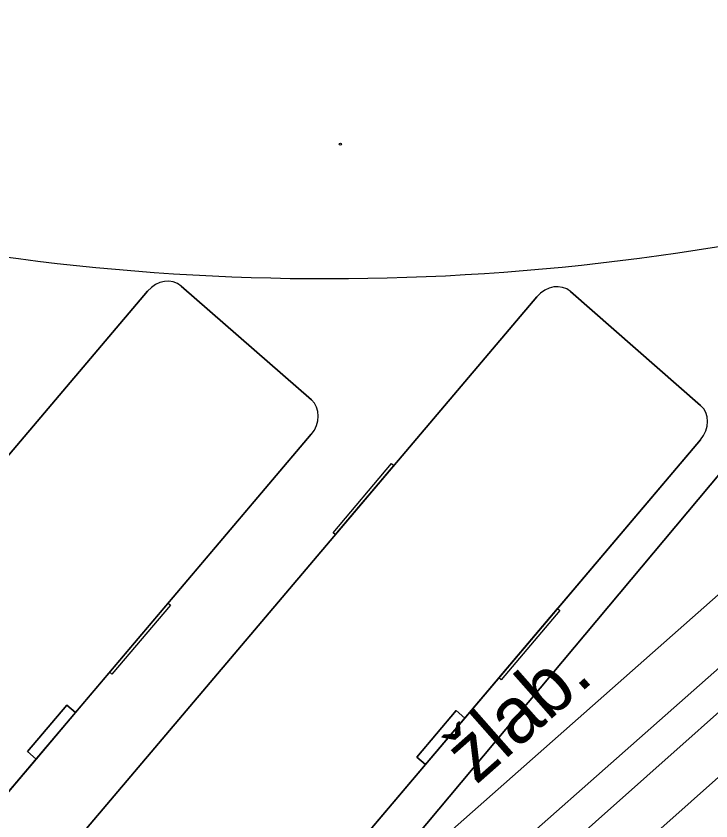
# Model space of a CAD drawing. Extents: x -438200 to -437954, y -1133133 to -1132850.
# Drawn here: x -438061.56 to -438053.53, y -1132985.78 to -1132976.48 of the extents above; entities that cross this region are included whole.
import ezdxf

# ---------------------------------------------------------------- set-up
doc = ezdxf.new("R2010")
doc.units = 0
for name, color, linetype in [('Vrstva 1', 7, 'Continuous'), ('Vrstva 10', 7, 'Continuous'), ('Vrstva 11', 7, 'Continuous'), ('Vrstva 40', 7, 'Continuous'), ('Vrstva 9', 7, 'Continuous')]:
    doc.layers.add(name, color=color, linetype=linetype)

msp = doc.modelspace()

# ---------------------------------------------------------------- linework, layer by layer
at = {"layer": 'Vrstva 1'}
for p, q in [((-438059.6486, -1132979.5983), (-438058.1432, -1132980.9139)), ((-438059.6486, -1132979.5983), (-438058.1432, -1132980.9139)), ((-438055.1494, -1132979.6617), (-438053.644, -1132980.9773)), ((-438055.1494, -1132979.6617), (-438053.644, -1132980.9773))]:
    msp.add_line(p, q, dxfattribs=at)
for points in [[(-438050.7956, -1132978.6286), (-438061.1166, -1132990.9482), (-438063.7995, -1132988.7005), (-438065.4554, -1132990.6771)], [(-438050.7956, -1132978.6286), (-438061.1166, -1132990.9482), (-438063.7995, -1132988.7005), (-438065.4554, -1132990.6771)], [(-438067.3665, -1132988.4439), (-438066.7172, -1132987.5398), (-438060.0358, -1132979.6582)], [(-438067.3665, -1132988.4439), (-438066.7172, -1132987.5398), (-438060.0358, -1132979.6582)], [(-438060.0358, -1132979.6582), (-438066.7172, -1132987.5398)], [(-438060.0358, -1132979.6582), (-438066.7172, -1132987.5398)], [(-438058.1432, -1132980.9139), (-438059.6486, -1132979.5983)], [(-438058.1432, -1132980.9139), (-438059.6486, -1132979.5983)], [(-438062.8673, -1132988.5073), (-438062.218, -1132987.6032), (-438055.5366, -1132979.7216)], [(-438062.8673, -1132988.5073), (-438062.218, -1132987.6032), (-438055.5366, -1132979.7216)], [(-438055.5366, -1132979.7216), (-438062.218, -1132987.6032)], [(-438055.5366, -1132979.7216), (-438062.218, -1132987.6032)], [(-438053.644, -1132980.9773), (-438055.1494, -1132979.6617)], [(-438053.644, -1132980.9773), (-438055.1494, -1132979.6617)], [(-438058.1439, -1132981.3115), (-438060.8697, -1132984.5269), (-438060.9692, -1132984.44), (-438061.4238, -1132984.9763), (-438061.3243, -1132985.0632), (-438064.8254, -1132989.1931), (-438064.8338, -1132989.2017), (-438064.9326, -1132989.1153), (-438065.4782, -1132989.6568), (-438065.3763, -1132989.7459), (-438065.6092, -1132989.9796)], [(-438058.1439, -1132981.3115), (-438060.8697, -1132984.5269), (-438060.9692, -1132984.44), (-438061.4238, -1132984.9763), (-438061.3243, -1132985.0632), (-438064.8254, -1132989.1931), (-438064.8338, -1132989.2017), (-438064.9326, -1132989.1153), (-438065.4782, -1132989.6568), (-438065.3763, -1132989.7459), (-438065.6092, -1132989.9796)], [(-438064.8254, -1132989.1931), (-438058.1439, -1132981.3115)], [(-438064.8254, -1132989.1931), (-438058.1439, -1132981.3115)], [(-438053.6447, -1132981.375), (-438056.3705, -1132984.5903), (-438056.47, -1132984.5034), (-438056.9246, -1132985.0397), (-438056.8251, -1132985.1266), (-438060.3262, -1132989.2566), (-438060.3347, -1132989.2651), (-438060.4334, -1132989.1788), (-438060.979, -1132989.7202), (-438060.8771, -1132989.8093), (-438061.11, -1132990.043)], [(-438053.6447, -1132981.375), (-438056.3705, -1132984.5903), (-438056.47, -1132984.5034), (-438056.9246, -1132985.0397), (-438056.8251, -1132985.1266), (-438060.3262, -1132989.2566), (-438060.3347, -1132989.2651), (-438060.4334, -1132989.1788), (-438060.979, -1132989.7202), (-438060.8771, -1132989.8093), (-438061.11, -1132990.043)], [(-438060.3262, -1132989.2566), (-438053.6447, -1132981.375)], [(-438060.3262, -1132989.2566), (-438053.6447, -1132981.375)]]:
    msp.add_lwpolyline(points, dxfattribs=at)
for points in [[(-438057.1896, -1132981.6715), (-438057.8669, -1132982.4706), (-438057.8929, -1132982.4478), (-438057.2156, -1132981.6488)], [(-438057.1896, -1132981.6715), (-438057.8669, -1132982.4706), (-438057.8929, -1132982.4478), (-438057.2156, -1132981.6488)], [(-438057.1896, -1132981.6715), (-438057.8486, -1132982.4489), (-438057.8486, -1132982.4489), (-438057.1896, -1132981.6715)], [(-438057.1896, -1132981.6715), (-438057.8486, -1132982.4489), (-438057.8486, -1132982.4489), (-438057.1896, -1132981.6715)], [(-438059.7709, -1132983.2842), (-438060.4483, -1132984.0832), (-438060.4743, -1132984.0605), (-438059.7969, -1132983.2614)], [(-438059.7709, -1132983.2842), (-438060.4483, -1132984.0832), (-438060.4743, -1132984.0605), (-438059.7969, -1132983.2614)], [(-438055.2717, -1132983.3476), (-438055.9491, -1132984.1466), (-438055.9751, -1132984.1239), (-438055.2977, -1132983.3248)], [(-438055.2717, -1132983.3476), (-438055.9491, -1132984.1466), (-438055.9751, -1132984.1239), (-438055.2977, -1132983.3248)], [(-438060.8697, -1132984.5269), (-438061.3243, -1132985.0632), (-438061.4238, -1132984.9763), (-438060.9692, -1132984.44)], [(-438060.8697, -1132984.5269), (-438061.3243, -1132985.0632), (-438061.4238, -1132984.9763), (-438060.9692, -1132984.44)], [(-438056.3705, -1132984.5903), (-438056.8251, -1132985.1266), (-438056.9246, -1132985.0397), (-438056.47, -1132984.5034)], [(-438056.3705, -1132984.5903), (-438056.8251, -1132985.1266), (-438056.9246, -1132985.0397), (-438056.47, -1132984.5034)]]:
    msp.add_lwpolyline(points, close=True, dxfattribs=at)
msp.add_circle((-438057.8079, -1132977.9596), 0.0127, dxfattribs=at)
msp.add_circle((-438057.8079, -1132977.9596), 0.0127, dxfattribs=at)
msp.add_circle((-438057.8079, -1132977.9596), 0.0127, dxfattribs=at)
msp.add_circle((-438057.8079, -1132977.9596), 0.0127, dxfattribs=at)
msp.add_arc((-438057.9618, -1132951.913), 27.6, 255.07669, 285.01553, dxfattribs=at)
msp.add_arc((-438057.9618, -1132951.913), 27.6, 255.07669, 285.01553, dxfattribs=at)
for centre, start_param, end_param in [((-438059.8425, -1132979.8271), 3.093695, 4.664491), ((-438059.8425, -1132979.8271), 3.093695, 4.664491), ((-438059.8425, -1132979.8271), 3.093695, 4.664491), ((-438059.8425, -1132979.8271), 3.093695, 4.664491), ((-438055.3434, -1132979.8905), 3.093695, 4.664491), ((-438055.3434, -1132979.8905), 3.093695, 4.664491), ((-438055.3434, -1132979.8905), 3.093695, 4.664491), ((-438055.3434, -1132979.8905), 3.093695, 4.664491), ((-438058.3371, -1132981.1427), 1.522899, 3.093695), ((-438058.3371, -1132981.1427), 1.522899, 3.093695), ((-438058.3371, -1132981.1427), 1.522899, 3.093695), ((-438058.3371, -1132981.1427), 1.522899, 3.093695), ((-438053.8379, -1132981.2061), 1.522899, 3.093695), ((-438053.8379, -1132981.2061), 1.522899, 3.093695), ((-438053.8379, -1132981.2061), 1.522899, 3.093695), ((-438053.8379, -1132981.2061), 1.522899, 3.093695)]:
    msp.add_ellipse(centre, major_axis=(-0.1845, -0.2366), ratio=0.855, start_param=start_param, end_param=end_param, dxfattribs=at)
at = {"layer": 'Vrstva 10'}
msp.add_lwpolyline([(-438035.457, -1132968.667), (-438040.579, -1132973.124), (-438048.857, -1132980.452), (-438065.053, -1132994.849), (-438072.69, -1133001.433), (-438073.961, -1133002.24), (-438075.077, -1133002.697), (-438076.272, -1133002.948)], dxfattribs=at)
at = {"layer": 'Vrstva 11'}
for points in [[(-438073.986, -1133001.3), (-438049.447, -1132979.638), (-438041.292, -1132972.525), (-438035.024, -1132966.82)], [(-438064.806, -1132994.051), (-438049.025, -1132980.119), (-438040.866, -1132973.003), (-438034.559, -1132967.262)]]:
    msp.add_lwpolyline(points, dxfattribs=at)
at = {"layer": 'Vrstva 40'}
for points in [[(-438082.3758, -1133013.7893), (-438066.4017, -1132994.506), (-438073.0336, -1132988.8171), (-438072.3528, -1132988.0234), (-438069.6652, -1132990.252), (-438068.2866, -1132988.6064), (-438065.6037, -1132990.8541), (-438063.7995, -1132988.7005), (-438061.1166, -1132990.9482), (-438050.7956, -1132978.6286), (-438047.7203, -1132977.5896), (-438045.2045, -1132976.3935), (-438042.6778, -1132974.8844), (-438040.928, -1132973.6336), (-438039.5901, -1132972.5144), (-438037.876, -1132970.8704), (-438035.3972, -1132967.8064), (-438020.0066, -1132954.1238)], [(-438075.9136, -1133005.9921), (-438066.4017, -1132994.506), (-438073.0336, -1132988.8171), (-438072.3528, -1132988.0234), (-438069.6652, -1132990.252), (-438068.2866, -1132988.6064), (-438065.6037, -1132990.8541), (-438063.7995, -1132988.7005), (-438061.1166, -1132990.9482), (-438050.7956, -1132978.6286), (-438047.7203, -1132977.5896), (-438045.2045, -1132976.3935), (-438042.6778, -1132974.8844), (-438040.928, -1132973.6336), (-438039.5901, -1132972.5144), (-438037.876, -1132970.8704), (-438035.3972, -1132967.8064), (-438020.0066, -1132954.1238)]]:
    msp.add_lwpolyline(points, dxfattribs=at)
at = {"layer": 'Vrstva 9'}
msp.add_lwpolyline([(-438046.991, -1132979.546), (-438048.487, -1132980.87), (-438063.628, -1132994.33)], dxfattribs=at)

# ---------------------------------------------------------------- texts
at = {"layer": 'Vrstva 40'}
msp.add_text('žlab.', height=0.65, rotation=41.43671, dxfattribs=at).set_placement((-438056.239, -1132985.367))

doc.saveas('drawing.dxf')
